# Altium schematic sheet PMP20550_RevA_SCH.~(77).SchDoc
size 431 x 279 mm; Date: Not shown in title block; ApprovedBy: Not shown in title block; CheckedBy: Not shown in title block; Author: Not shown in title block; CompanyName: Not shown in title block; Engineer: Not shown in title block; Organization: Not shown in title block; Address1: Not shown in title block; Address2: Not shown in title block; Address3: Not shown in title block; Address4: Not shown in title block; DocumentNumber: 1; Revision: Use project parameter SCH_Rev; SheetNumber: 2; SheetTotal: 3; PageSetup: Record=PageOptions¦CenterHorizontal=True¦CenterVertical=True¦PrintScale=1.00¦XCorrection=1.00¦YCorrection=1.00¦PrintKind=0¦BorderSize=5000000¦LeftOffset=0¦BottomOffset=0¦Orientation=2¦PaperLength=1000¦PaperWidth=1000¦Scale=100¦PaperSource=15¦PrintQuality=600¦MediaType=1¦DitherType=10¦PaperKind=Letter¦PrintScaleMode=1
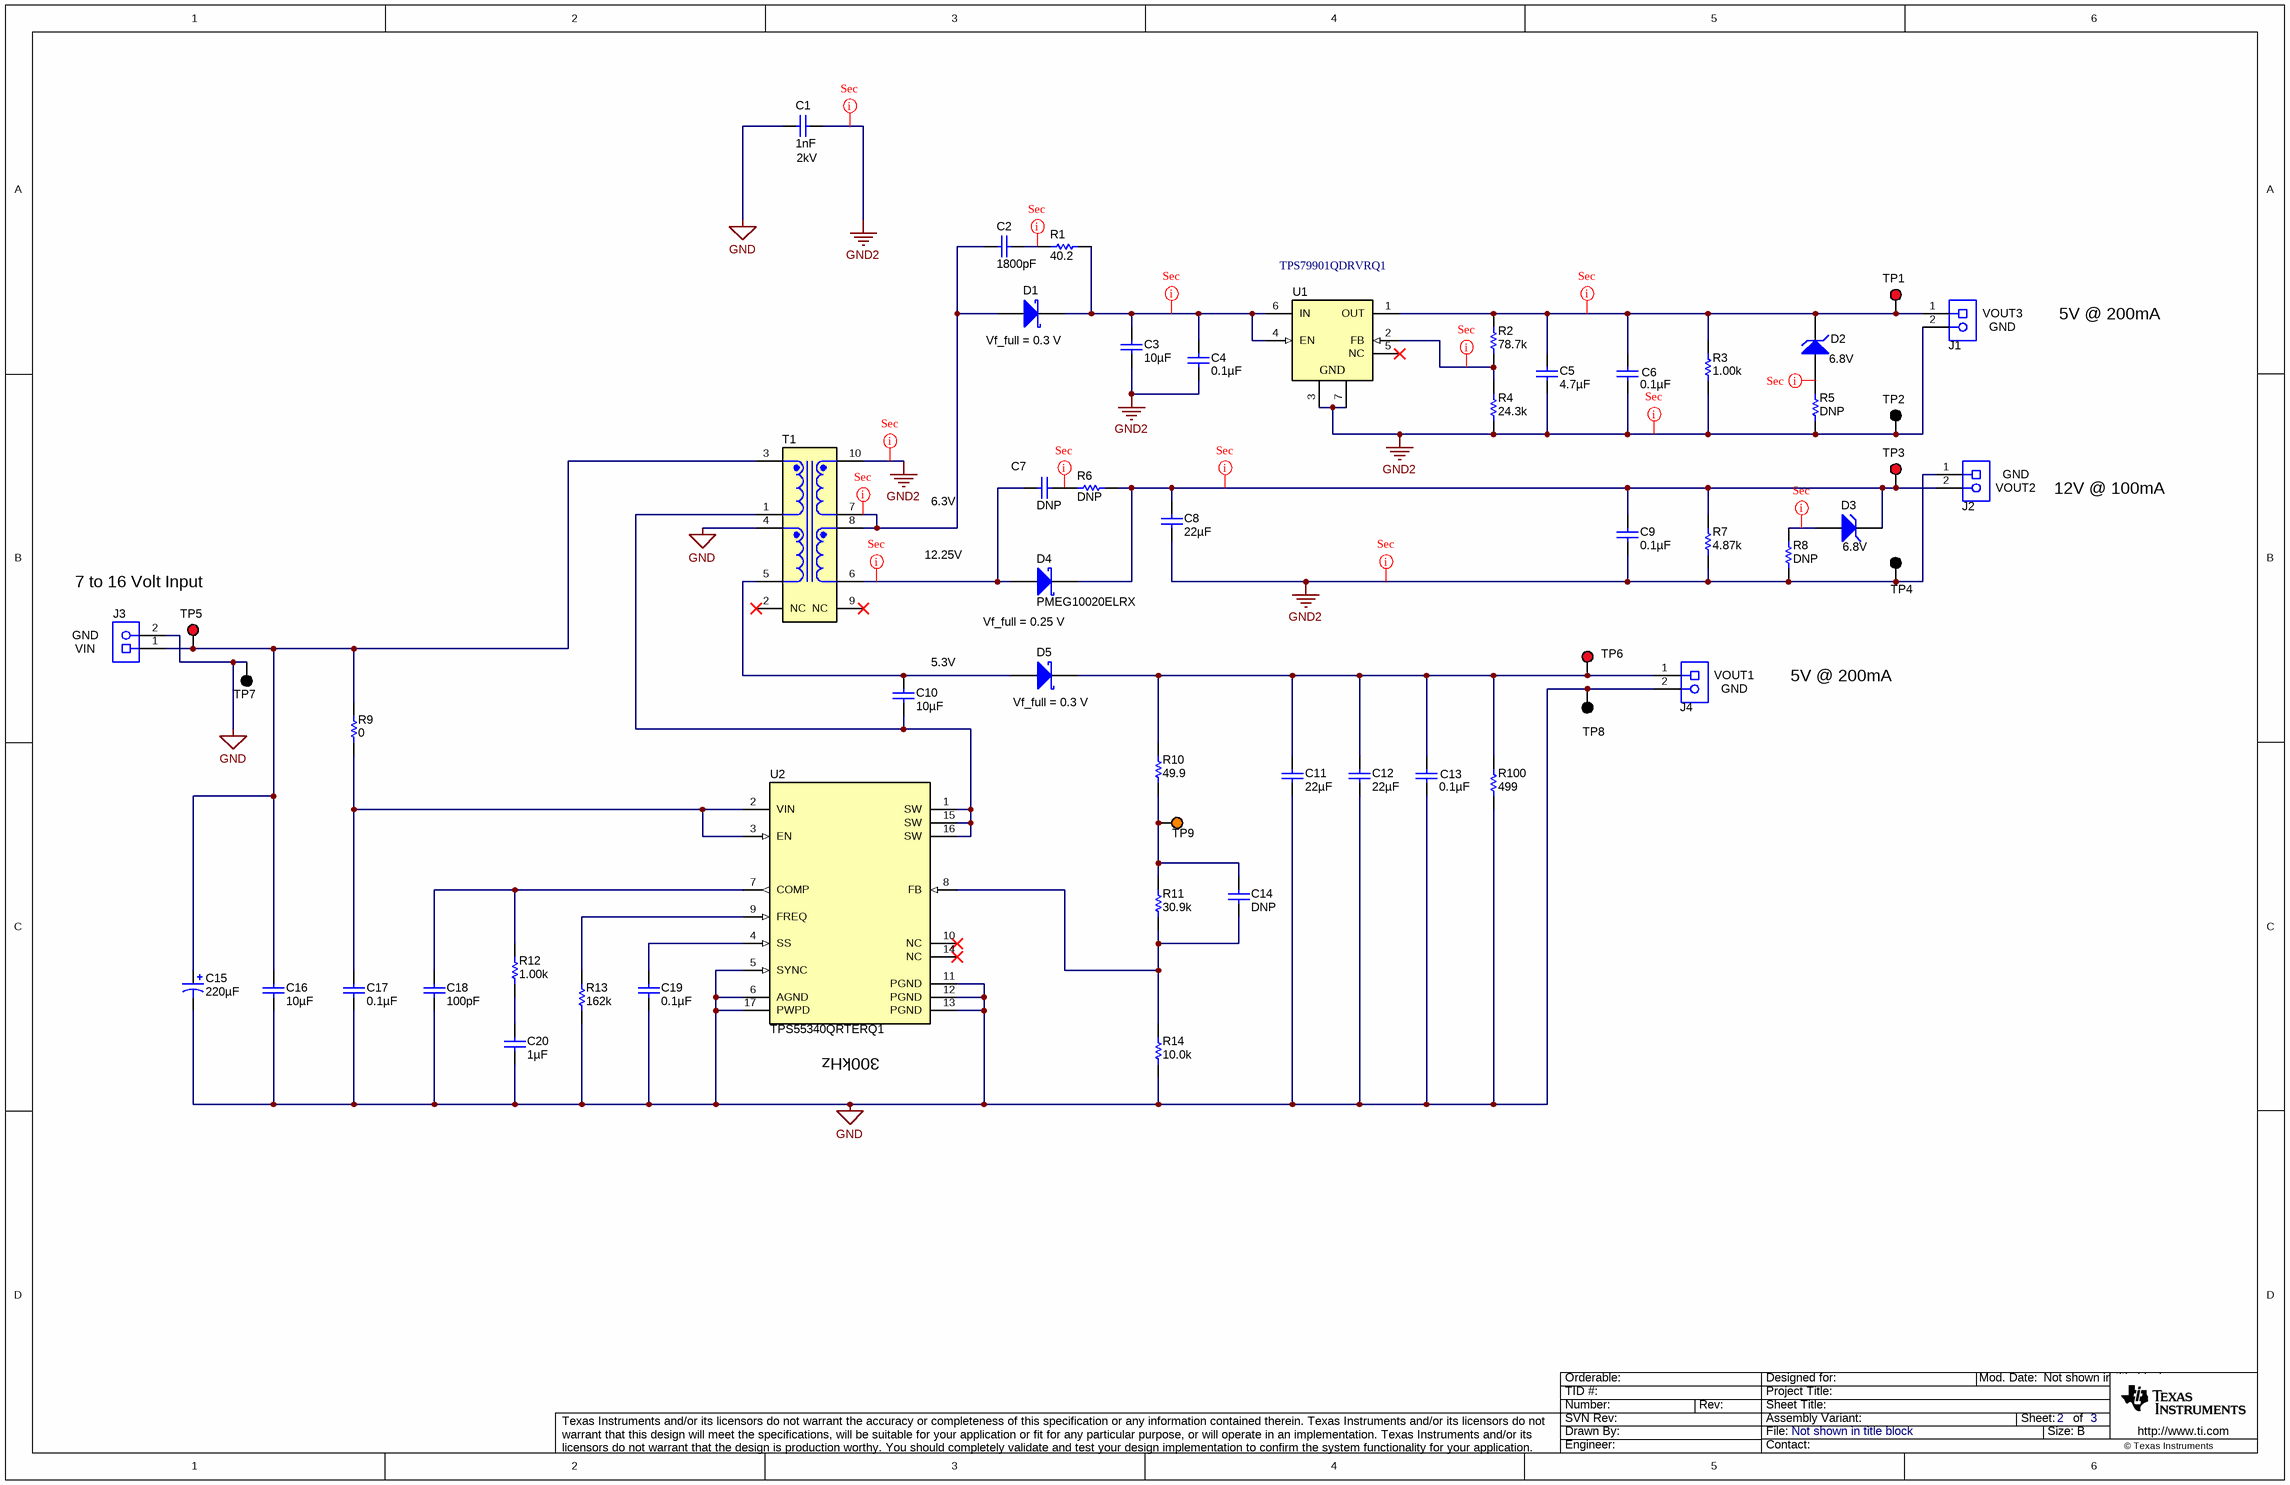
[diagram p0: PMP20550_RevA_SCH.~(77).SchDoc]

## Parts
C1  ValueDisplayed: 1nF  Value2: 2kV  [1812]  (hidden comment: GR443QR73D102KW01L)
C2  ValueDisplayed: 1800pF  [0603]  (hidden comment: GRM1885C1H182JA01D)
C3  ValueDisplayed: 10µF  [0603]  (hidden comment: GRM188Z71A106MA73D)
C4  ValueDisplayed: 0.1µF  [0603]  (hidden comment: C1608X7R1E104K080AA)
C5  ValueDisplayed: 4.7µF  [0805_HV]  (hidden comment: C2012X7R1E474K125AA)
C6  ValueDisplayed: 0.1µF  [0603]  (hidden comment: C0603X104K8RACTU)
C7  ValueDisplayed: DNP  [0603]  (hidden comment: GRM1885C1H111JA01D)
C8  ValueDisplayed: 22µF  [1210_280]  (hidden comment: 12103D226MAT2A)
C9  ValueDisplayed: 0.1µF  [0603]  (hidden comment: GRM188R71H104KA93D)
C10  ValueDisplayed: 10µF  [0805_HV]  (hidden comment: GRM21BR6YA106KE43L)
C11  ValueDisplayed: 22µF  [0805_HV]  (hidden comment: GRM21BZ71A226ME15L)
C12  ValueDisplayed: 22µF  [0805_HV]  (hidden comment: GRM21BZ71A226ME15L)
C13  ValueDisplayed: 0.1µF  [0603]  (hidden comment: C0603X104K8RACTU)
C14  ValueDisplayed: DNP  [0402]  (hidden comment: GRM1555C1H201JA01D)
C15  ValueDisplayed: 220µF  [SM_RADIAL_G]  (hidden comment: EEE-FC1V221P)
C16  ValueDisplayed: 10µF  [1206]  (hidden comment: GMK316AB7106KL)
C17  ValueDisplayed: 0.1µF  [0603]  (hidden comment: C1608X7R1E104K080AA)
C18  ValueDisplayed: 100pF  [0603]  (hidden comment: CGA3E2NP01H101J080AA)
C19  ValueDisplayed: 0.1µF  [0603]  (hidden comment: C1608X7R1E104K080AA)
C20  ValueDisplayed: 1µF  [0603]  (hidden comment: UMK107AB7105KA-T)
D1  PMEG2020EJ,115  [SOD-323F]  (value not drawn)
D2  value 6.8V  [SOD-323]  (hidden comment: MMSZ5235BS-7-F)
D3  value 6.8V  [SOD-323]  (hidden comment: MMSZ5235BS-7-F)
D4  PMEG10020ELRX  [SOD-123W]
D5  PMEG2020EJ,115  [SOD-323F]  (value not drawn)
J1  1984617  [Phoenix_1984617]  (value not drawn)
J2  1984617  [Phoenix_1984617]  (value not drawn)
J3  1984617  [Phoenix_1984617]  (value not drawn)
J4  1984617  [Phoenix_1984617]  (value not drawn)
R1  ValueDisplayed: 40.2  [0603]  (hidden comment: CRCW060340R2FKEA)
R2  ValueDisplayed: 78.7k  [0603]  (hidden comment: RC0603FR-0778K7L)
R3  ValueDisplayed: 1.00k  [0805_HV]  (hidden comment: RT0805BRD071KL)
R4  ValueDisplayed: 24.3k  [0603]  (hidden comment: RT0603DRE0724K3L)
R5  ValueDisplayed: DNP  [0603]  (hidden comment: CPF0603B1K62E)
R6  ValueDisplayed: DNP  [0603]  (hidden comment: CPF0603B1K62E)
R7  ValueDisplayed: 4.87k  [0805_HV]  (hidden comment: ERJ-6ENF4871V)
R8  ValueDisplayed: DNP  [0603]  (hidden comment: CPF0603B1K62E)
R9  ValueDisplayed: 0  [0603]  (hidden comment: ERJ-3GEY0R00V)
R10  ValueDisplayed: 49.9  [0402]  (hidden comment: ERJ-2RKF49R9X)
R11  ValueDisplayed: 30.9k  [0603]  (hidden comment: CRCW060330K9FKEA)
R12  ValueDisplayed: 1.00k  [0603]  (hidden comment: RT0603BRB071KL)
R13  ValueDisplayed: 162k  [0603]  (hidden comment: CRCW0603162KFKEA)
R14  ValueDisplayed: 10.0k  [0402]  (hidden comment: ERJ-2RKF1002X)
R100  ValueDisplayed: 499  [0805_HV]  (hidden comment: RT0805BRD07499RL)
T1  750316553  [Wurth_750316553]  (value not drawn)
TP1  5000  [Keystone5000]  (value not drawn)
TP2  5001  [Keystone5001]  (value not drawn)
TP3  5000  [Keystone5000]  (value not drawn)
TP4  5001  [Keystone5001]  (value not drawn)
TP5  5000  [Keystone5000]  (value not drawn)
TP6  VBUS  [Keystone5000]  (value not drawn)
TP7  5001  [Keystone5001]  (value not drawn)
TP8  5001  [Keystone5001]  (value not drawn)
TP9  5003  [Keystone5003]  (value not drawn)
U1  TPS79901QDRVRQ1  [DRV0006A]
U2  TPS55340QRTERQ1  [RTE0016C]

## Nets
GND: C1.2 C11.2 C12.2 C13.2 C15.2(-) C16.2 C17.2 C18.2 C19.2 C20.2 J3.2 J4.2 R13.1 R14.1 R100.1 T1.4 TP7.1 TP8.1 U2.5(SYNC) U2.6(AGND) U2.11(PGND) U2.12(PGND) U2.13(PGND) U2.17(PWPD)
GND2: C1.1 C3.2 C4.2 C5.2 C6.2 C8.2 C9.2 J1.2 J2.1 R3.1 R4.1 R5.2 R7.1 R8.2 T1.10 TP2.1 TP4.1 U1.3(GND) U1.7(GND)
NetC2_1: C2.1 R1.1
NetC2_2: C2.2 D1.2(A) T1.7 T1.8
NetC3_1: C3.1 C4.1 D1.1(K) R1.2 U1.4(EN) U1.6(IN)
NetC5_1: C5.1 C6.1 D2.1(K) J1.1 R2.2 R3.2 TP1.1 U1.1(OUT)
NetC7_1: C7.1 R6.2
NetC7_2: C7.2 D4.2(A) T1.6
NetC8_1: C8.1 C9.1 D3.1(K) D4.1(K) J2.2 R6.1 R7.2 TP3.1
NetC10_1: C10.1 D5.2(A) T1.5
NetC10_2: C10.2 T1.1 U2.1(SW) U2.15(SW) U2.16(SW)
NetC11_1: C11.1 C12.1 C13.1 D5.1(K) J4.1 R10.2 R100.2 TP6.1
NetC14_1: C14.1 R10.1 R11.2 TP9.1
NetC14_2: C14.2 R11.1 R14.2 U2.8(FB)
NetC15_1: C15.1(+) C16.1 J3.1 R9.2 T1.3 TP5.1
NetC17_1: C17.1 R9.1 U2.2(VIN) U2.3(EN)
NetC18_1: C18.1 R12.2 U2.7(COMP)
NetC19_1: C19.1 U2.4(SS)
NetC20_1: C20.1 R12.1
NetD2_2: D2.2(A) R5.1
NetD3_2: D3.2(A) R8.1
NetR2_1: R2.1 R4.2 U1.2(FB)
NetR13_2: R13.2 U2.9(FREQ)

Not connected (* = marked no-connect by the designer): T1 2(NC)* 9(NC)*; U1 5(NC)*; U2 10(NC)* 14(NC)*

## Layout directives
net class Undefined: GND2, NetC2_1, NetC2_2, NetC3_1, NetC5_1, NetC7_1, NetC7_2, NetC8_1, NetD2_2, NetD3_2, NetR2_1

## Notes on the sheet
- (near D1) Vf_full = 0.3 V
- (near J1) VOUT3
- (near J1) GND
- 5V @ 200mA
- 6.3V
- (near J2) VOUT2
- (near J2) GND
- 12V @ 100mA
- 12.25V
- (near J3) GND
- 7 to 16 Volt Input
- Vf_full = 0.25 V
- (near J3) VIN
- (near C10) 5.3V
- (near D5) Vf_full = 0.3 V
- (near J4) VOUT1
- (near J4) GND
- (near U2) 300kHz

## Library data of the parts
C1 = GR443QR73D102KW01L: CAP, CERM, 1000 pF, 2000 V, +/- 10%, X7R, 1812; Manufacturer: MuRata; Polarized: N; CompType: Capacitor; Value: 1000pF; U/M: EA; Cap_F: 0.000000001; Tolerance_%: 10; Value1: Unknown; VDC_V: 2000; TaMin_C: -55; TaMax_C: 125; SizeArea_mm2: 14.4; SizeAreaWB_mm2: 23.1; SizeX_mm: 4.5; SizeY_mm: 3.2; SizeZ_mm: 1.35; AEC Category: Q200
C2 = GRM1885C1H182JA01D: CAP, CERM, 1800 pF, 50 V, +/- 5%, C0G/NP0, 0603; Manufacturer: MuRata; Polarized: N; CompType: Capacitor; Value: 1800pF; U/M: EA; Cap_F: 0.0000000018; Tolerance_%: 5; Value1: Unknown; VDC_V: 50; Value2: 50V; TaMin_C: -55; TaMax_C: 125; SizeArea_mm2: 1.28; SizeAreaWB_mm2: 4.68; SizeX_mm: 1.6; SizeY_mm: 0.8; SizeZ_mm: 1; AEC Category: Q200
C3 = GRM188Z71A106MA73D: CAP, CERM, 10 µF, 10 V, +/- 20%, X7R, 0603; Manufacturer: MuRata; Polarized: N; CompType: Capacitor; Value: 10uF; U/M: EA; Cap_F: 0.00001; Tolerance_%: 20; Value1: Unknown; VDC_V: 10; Value2: 10V; TaMin_C: -55; TaMax_C: 125; SizeArea_mm2: 1.28; SizeAreaWB_mm2: 4.68; SizeX_mm: 1.6; SizeY_mm: 0.8; SizeZ_mm: 1; AEC Category: Q200
C4 C17 C19 = C1608X7R1E104K080AA: CAP, CERM, 0.1 µF, 25 V, +/- 10%, X7R, 0603; Manufacturer: TDK; Polarized: N; CompType: Capacitor; Value: 0.1uF; U/M: EA; Cap_F: 0.0000001; Tolerance_%: 10; Value1: Unknown; VDC_V: 25; Value2: 25V; TaMin_C: -55; TaMax_C: 125; SizeArea_mm2: 1.28; SizeAreaWB_mm2: 4.68; SizeX_mm: 1.6; SizeY_mm: 0.8; SizeZ_mm: 1; AEC Category: Q200
C5 = C2012X7R1E474K125AA: CAP, CERM, 4.7 µF, 25 V, +/- 10%, X7R, 0805; Manufacturer: TDK; Polarized: N; CompType: Capacitor; Value: 4.7uF; U/M: EA; Cap_F: 0.0000047; Tolerance_%: 10; Value1: Unknown; VDC_V: 25; Value2: 25V; TaMin_C: -55; TaMax_C: 125; Cap_Case: 0805; SizeArea_mm2: 2.5; SizeAreaWB_mm2: 6.75; SizeX_mm: 2; SizeY_mm: 1.25; SizeZ_mm: 1.45; AEC Category: Q200
C6 C13 = C0603X104K8RACTU: CAP, CERM, 0.1 µF, 10 V, +/- 10%, X7R, 0603; Manufacturer: Kemet; Polarized: N; CompType: Capacitor; Value: 0.1uF; U/M: EA; Cap_F: 0.0000001; Tolerance_%: 10; Value1: Unknown; Value2: 10V; TaMin_C: -55; TaMax_C: 125; SizeArea_mm2: 1.28; SizeAreaWB_mm2: 4.68; SizeX_mm: 1.6; SizeY_mm: 0.8; SizeZ_mm: 1; AEC Category: Q200
C7 = GRM1885C1H111JA01D: CAP, CERM, 110 pF, 50 V, +/- 5%, C0G/NP0, 0603; Manufacturer: MuRata; Polarized: N; CompType: Capacitor; Value: 110pF; U/M: EA; Cap_F: 0.00000000011; Tolerance_%: 5; Value1: Unknown; VDC_V: 50; Value2: 50V; TaMin_C: -55; TaMax_C: 125; SizeArea_mm2: 1.28; SizeAreaWB_mm2: 4.68; SizeX_mm: 1.6; SizeY_mm: 0.8; SizeZ_mm: 1; AEC Category: Q200
C8 = 12103D226MAT2A: CAP, CERM, 22 µF, 25 V, +/- 20%, X5R, 1210; Manufacturer: AVX; Polarized: N; CompType: Capacitor; Value: 22uF; U/M: EA; Cap_F: 0.000022; Tolerance_%: 20; Value1: Unknown; VDC_V: 25; Value2: 25V; TaMin_C: -55; TaMax_C: 85; Cap_Case: 1210; SizeArea_mm2: 8; SizeAreaWB_mm2: 14.7; SizeX_mm: 3.2; SizeY_mm: 2.5; SizeZ_mm: 2.8; AEC Category: Q200
C9 = GRM188R71H104KA93D: CAP, CERM, 0.1 µF, 50 V, +/- 10%, X7R, 0603; Manufacturer: MuRata; Polarized: N; CompType: Capacitor; Value: 0.1uF; U/M: EA; Cap_F: 0.0000001; Tolerance_%: 10; Value1: Unknown; VDC_V: 50; Value2: 50V; TaMin_C: -55; TaMax_C: 125; SizeArea_mm2: 1.28; SizeAreaWB_mm2: 4.68; SizeX_mm: 1.6; SizeY_mm: 0.8; SizeZ_mm: 1; AEC Category: Q200
C10 = GRM21BR6YA106KE43L: CAP, CERM, 10 µF, 35 V, +/- 10%, X5R, 0805; Manufacturer: MuRata; Polarized: N; CompType: Capacitor; Value: 10uF; U/M: EA; Cap_F: 0.00001; Tolerance_%: 10; Value1: Unknown; VDC_V: 35; Value2: 35V; TaMin_C: -55; TaMax_C: 85; Cap_Case: 0805; SizeArea_mm2: 2.5; SizeAreaWB_mm2: 6.75; SizeX_mm: 2; SizeY_mm: 1.25; SizeZ_mm: 1.45; AEC Category: Q200
C11 C12 = GRM21BZ71A226ME15L: CAP, CERM, 22 µF, 10 V, +/- 20%, X7R, 0805; Manufacturer: MuRata; Polarized: N; CompType: Capacitor; Value: 22uF; U/M: EA; Cap_F: 0.000022; Tolerance_%: 20; Value1: Unknown; VDC_V: 10; Value2: 10V; TaMin_C: -55; TaMax_C: 125; Cap_Case: 0805; SizeArea_mm2: 2.5; SizeAreaWB_mm2: 6.75; SizeX_mm: 2; SizeY_mm: 1.25; SizeZ_mm: 1.45; AEC Category: Q200
C14 = GRM1555C1H201JA01D: CAP, CERM, 200 pF, 50 V, +/- 5%, C0G/NP0, 0402; Manufacturer: MuRata; Polarized: N; CompType: Capacitor; Value: 200pF; U/M: EA; Cap_F: 0.0000000002; Tolerance_%: 5; Value1: Unknown; VDC_V: 50; Value2: 50V; TaMin_C: -55; TaMax_C: 125; SizeArea_mm2: 0.5; SizeAreaWB_mm2: 3; SizeX_mm: 1; SizeZ_mm: 0.6; AEC Category: Q200
C15 = EEE-FC1V221P: CAP, AL, 220 µF, 35 V, +/- 20%, 0.15 ohm, SMD; Manufacturer: Panasonic; Polarized: Y; CompType: Capacitor; Value: 220uF; U/M: EA; Cap_F: 0.00022; Tolerance_%: 20; VDC_V: 35; Value2: 35V; ESR_ohm: 0.15; IRMS_A: 0.67; TaMin_C: -40; TaMax_C: 105; Cap_Case: G; SizeAreaWB_mm2: 172.2; SizeArea_mm2: 123.6; SizeX_mm: 12; SizeY_mm: 10.3; SizeZ_mm: 10.2; AEC Category: Q200
C16 = GMK316AB7106KL: CAP, CERM, 10 µF, 35 V, +/- 10%, X7R, 1206; Manufacturer: Taiyo Yuden; Polarized: N; CompType: Capacitor; Value: 10uF; U/M: EA; Cap_F: 0.00001; Tolerance_%: 10; Value1: Unknown; VDC_V: 35; Value2: 35V; TaMin_C: -55; TaMax_C: 125; SizeArea_mm2: 5.12; SizeAreaWB_mm2: 10.92; SizeX_mm: 3.2; SizeY_mm: 1.6; SizeZ_mm: 1.35; AEC Category: Q200
C18 = CGA3E2NP01H101J080AA: CAP, CERM, 100 pF, 50 V, +/- 5%, C0G/NP0, AEC-Q200 Grade 0, 0603; Manufacturer: TDK; Polarized: N; CompType: Capacitor; Value: 100pF; U/M: EA; Cap_F: 0.0000000001; Tolerance_%: 5; Value1: Unknown; VDC_V: 50; Value2: 50V; TaMin_C: -55; TaMax_C: 150; SizeArea_mm2: 1.28; SizeAreaWB_mm2: 4.68; SizeX_mm: 1.6; SizeY_mm: 0.8; SizeZ_mm: 1; AEC Category: Q200; AEC Qualified: Y; AEC Grade: 0
C20 = UMK107AB7105KA-T: CAP, CERM, 1 µF, 50 V, +/- 10%, X7R, 0603; Manufacturer: Taiyo Yuden; Polarized: N; CompType: Capacitor; Value: 1uF; U/M: EA; Cap_F: 0.000001; Tolerance_%: 10; Value1: Unknown; VDC_V: 50; Value2: 50V; TaMin_C: -55; TaMax_C: 125; SizeArea_mm2: 1.28; SizeAreaWB_mm2: 4.68; SizeX_mm: 1.6; SizeY_mm: 0.8; SizeZ_mm: 1; AEC Category: Q200
D1 D5 = PMEG2020EJ,115: Diode, Schottky, 20 V, 2 A, SOD-323F; Manufacturer: NXP Semiconductor; U/M: EA; Vf_V: 0.525; Value: 20V; Value1: 2A; Value2: 0.525V; Io_A: 2; Vr_V: 20; TJmax_C: 150; SizeAreaWB_mm2: 7.875; SizeArea_mm2: 3.125; SizeX_mm: 2.5; SizeY_mm: 1.25; SizeZ_mm: 0.8; AEC Category: Q101; AEC Qualified: N
D2 D3 = MMSZ5235BS-7-F: Diode, Zener, 6.8 V, 200 mW, SOD-323; Manufacturer: Diodes Inc.; SymbolCreator: a0412235; U/M: EA; Power_W: 0.2; Vz_V: 6.8; Value1: 0.2W; RJA_CperW: 350; SizeAreaWB_mm2: 8.695; SizeArea_mm2: 3.645; SizeX_mm: 2.7; SizeY_mm: 1.35; SizeZ_mm: 1; AEC Category: Q101
D4 = PMEG10020ELRX: Diode, Schottky, 100 V, 2 A, AEC-Q101, SOD-123W; Manufacturer: NXP Semiconductor; U/M: EA; Vf_V: 0.83; Value: 100V; Value1: 2A; Value2: 0.83V; Io_A: 2; Vr_V: 100; TJmax_C: 175; SizeAreaWB_mm2: 12.15; SizeArea_mm2: 5.95; SizeX_mm: 3.5; SizeY_mm: 1.7; SizeZ_mm: 1; AEC Category: Q101; AEC Qualified: Y
J1-J4 = 1984617: Terminal Block, 3.5mm, 2x1, TH; Manufacturer: Phoenix Contact; SymbolCreator: a0412235; Pitch_mm: 3.5; Gender: Female; Row_Count: 1; Current_A: 17.5; Voltage_V: 200; Cert_UL: Y
R1 = CRCW060340R2FKEA: RES, 40.2, 1%, 0.1 W, 0603; Manufacturer: Vishay-Dale; CompType: Resistor; Value: 40.2; Value_Code: 40R2; Tolerance_%: 1; Power_W: 0.1; Value2: 0.1W; VDC_V: 75; TempCo: 100 ppm/C; SizeArea_mm2: 1.28; SizeX_mm: 1.6; SizeY_mm: 0.8; EIA_Code: E96; U/M: EA; AEC Category: Q200
R2 = RC0603FR-0778K7L: RES, 78.7 k, 1%, 0.1 W, 0603; Manufacturer: Yageo America; CompType: Resistor; Value: 78.7k; Res_ohm: 78700; Value_Code: 78k7; Tolerance_%: 1; Power_W: 0.1; Value2: 0.1W; VDC_V: 150; TempCo: 200 ppm/C; SizeArea_mm2: 1.28; SizeX_mm: 1.6; SizeY_mm: 0.8; EIA_Code: E96; U/M: EA; AEC Category: Q200
R3 = RT0805BRD071KL: RES, 1.00 k, 0.1%, 0.125 W, 0805; Manufacturer: Yageo America; CompType: Resistor; Value: 1.00k; Res_ohm: 1000; Value_Code: 1k00; Tolerance_%: 0.1; Power_W: 0.125; Value2: 0.125W; VDC_V: 150; TempCo: 25 ppm/C; SizeArea_mm2: 2.5; SizeX_mm: 2; SizeY_mm: 1.25; SizeZ_mm: 1.45; EIA_Code: E192; U/M: EA; AEC Category: Q200
R4 = RT0603DRE0724K3L: RES, 24.3 k, 0.5%, 0.1 W, 0603; Manufacturer: Yageo America; CompType: Resistor; Value: 24.3k; Res_ohm: 24300; Value_Code: 24k3; Tolerance_%: 0.5; Power_W: 0.1; Value2: 0.1W; VDC_V: 75; TempCo: 50 ppm/C; SizeArea_mm2: 1.28; SizeX_mm: 1.6; SizeY_mm: 0.8; SizeZ_mm: 1; EIA_Code: E192; U/M: EA; AEC Category: Q200
R5 R6 R8 = CPF0603B1K62E: RES, 1.62 k, 0.1%, 0.063 W, 0603; Manufacturer: TE Connectivity; CompType: Resistor; Value: 1.62k; Res_ohm: 1620; Value_Code: 1k62; Tolerance_%: 0.1; Power_W: 0.063; Value2: 0.063W; VDC_V: 50; TempCo: 25 ppm/C; SizeArea_mm2: 1.28; SizeX_mm: 1.6; SizeY_mm: 0.8; SizeZ_mm: 1; EIA_Code: E192; U/M: EA; AEC Category: Q200
R7 = ERJ-6ENF4871V: RES, 4.87 k, 1%, 0.125 W, 0805; Manufacturer: Panasonic; CompType: Resistor; Value: 4.87k; Res_ohm: 4870; Value_Code: 4k87; Tolerance_%: 1; Power_W: 0.125; Value2: 0.125W; TempCo: 100 ppm/C; SizeArea_mm2: 2.5; SizeX_mm: 2; SizeY_mm: 1.25; SizeZ_mm: 1.45; EIA_Code: E96; U/M: EA; AEC Category: Q200
R9 = ERJ-3GEY0R00V: RES, 0, 5%, 0.1 W, 0603; Manufacturer: Panasonic; CompType: Resistor; Value: 0; Value_Code: 0000; Tolerance_%: 5; Power_W: 0.1; Value2: 0.1W; VDC_V: 50; TempCo: 600 ppm/C; SizeArea_mm2: 1.28; SizeX_mm: 1.6; SizeY_mm: 0.8; SizeZ_mm: 1; EIA_Code: E24; U/M: EA; AEC Category: Q200
R10 = ERJ-2RKF49R9X: RES, 49.9, 1%, 0.1 W, AEC-Q200 Grade 0, 0402; Manufacturer: Panasonic; CompType: Resistor; Value: 49.9; Value_Code: 49R9; Tolerance_%: 1; Power_W: 0.1; Value2: 0.1W; VDC_V: 50; TempCo: 100 ppm/C; SizeArea_mm2: 0.5; SizeZ_mm: 0.6; EIA_Code: E96; U/M: EA; AEC Category: Q200; AEC Qualified: Y; AEC Grade: 0
R11 = CRCW060330K9FKEA: RES, 30.9 k, 1%, 0.1 W, 0603; Manufacturer: Vishay-Dale; CompType: Resistor; Value: 30.9k; Res_ohm: 30900; Value_Code: 30k9; Tolerance_%: 1; Power_W: 0.1; Value2: 0.1W; VDC_V: 75; TempCo: 100 ppm/C; SizeArea_mm2: 1.28; SizeX_mm: 1.6; SizeY_mm: 0.8; EIA_Code: E96; U/M: EA; AEC Category: Q200
R12 = RT0603BRB071KL: RES, 1.00 k, 0.1%, 0.1 W, 0603; Manufacturer: Yageo America; CompType: Resistor; Value: 1.00k; Res_ohm: 1000; Value_Code: 1k00; Tolerance_%: 0.1; Value2: 0.1W; VDC_V: 75; TempCo: 10 ppm/C; SizeArea_mm2: 1.28; SizeX_mm: 1.6; SizeY_mm: 0.8; SizeZ_mm: 1; EIA_Code: E192; U/M: EA; AEC Category: Q200; AEC Qualified: N
R13 = CRCW0603162KFKEA: RES, 162 k, 1%, 0.1 W, 0603; Manufacturer: Vishay-Dale; CompType: Resistor; Value: 162k; Res_ohm: 162000; Tolerance_%: 1; Power_W: 0.1; Value2: 0.1W; VDC_V: 75; TempCo: 100 ppm/C; SizeArea_mm2: 1.28; SizeX_mm: 1.6; SizeY_mm: 0.8; EIA_Code: E96; U/M: EA; AEC Category: Q200
R14 = ERJ-2RKF1002X: RES, 10.0 k, 1%, 0.1 W, 0402; Manufacturer: Panasonic; CompType: Resistor; Value: 10.0k; Res_ohm: 10000; Value_Code: 10k0; Tolerance_%: 1; Power_W: 0.1; Value2: 0.1W; VDC_V: 50; TempCo: 100 ppm/C; SizeArea_mm2: 0.5; SizeZ_mm: 0.6; EIA_Code: E96; U/M: EA; AEC Category: Q200
R100 = RT0805BRD07499RL: RES, 499, 0.1%, 0.125 W, 0805; Manufacturer: Yageo America; CompType: Resistor; Value: 499; Value_Code: 499R; Tolerance_%: 0.1; Power_W: 0.125; Value2: 0.125W; VDC_V: 150; TempCo: 25 ppm/C; SizeArea_mm2: 2.5; SizeX_mm: 2; SizeY_mm: 1.25; SizeZ_mm: 1.45; EIA_Code: E192; U/M: EA; AEC Category: Q200
T1 = 750316553: Transformer, 52 uH, SMT; Manufacturer: Wurth Elektronik; SymbolCreator: Altium; Lp: 52; DCR_ohm: 0.065; Ns1toNp: 1.19; Ns2toNp: 1.13; Rs1: 0.09; Rs2: 0.085; SizeAreaWB_mm2: 305.335; SizeArea_mm2: 238.915; SizeX_mm: 17.75; SizeY_mm: 13.46; SizeZ_mm: 12.7
TP1 TP3 TP5 = 5000: Test Point, Miniature, Red, TH; Manufacturer: Keystone; CompType: Test Point Loop; ContactFinish: Silver
TP2 TP4 TP7 TP8 = 5001: Test Point, Miniature, Black, TH; Manufacturer: Keystone; CompType: Test Point Loop; ContactFinish: Silver
TP6 = 5000: Test Point, TH, Miniature, Red; Manufacturer: Keystone; CompType: Test Point Loop; U/M: EA
TP9 = 5003: Test Point, Miniature, Orange, TH; Manufacturer: Keystone; CompType: Test Point Loop; ContactFinish: Silver
U1 = TPS79901QDRVRQ1: Single Output High PSRR LDO, 200 mA, Adjustable 1.2 to 6.5 V Output, 2.7 to 6.5 V Input, with Low IQ, 6-pin SON (DRV), -40 to 125 degC, Green (RoHS & no Sb/Br); Manufacturer: Texas Instruments; Alternate PartNumber: Equivalent; Accuracy(%): 2; Iout(Max)(A): 0.2; Iq(Typ)(mA): 0.04; Rating: Automotive; SubFamily: Single Channel LDO; Vdo(Typ)(mV): 90; Vin(Max)(V): 6.5; Vin(Min)(V): 2.7; Vout Adj(Min)(V): 1.2
U2 = TPS55340QRTERQ1: Integrated 5-A 40-V Wide Input Range Boost/SEPIC/Flyback DC-DC Regulator, RTE0016C; Alternate PartNumber: TPS55340QRTETQ1; Manufacturer: Texas Instruments; SymbolCreator: x0208326; SizeArea_mm2: 9; SizeAreaWB_mm2: 16; SizeX_mm: 3; SizeZ_mm: 0.8; CompType: IC; U/M: EA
